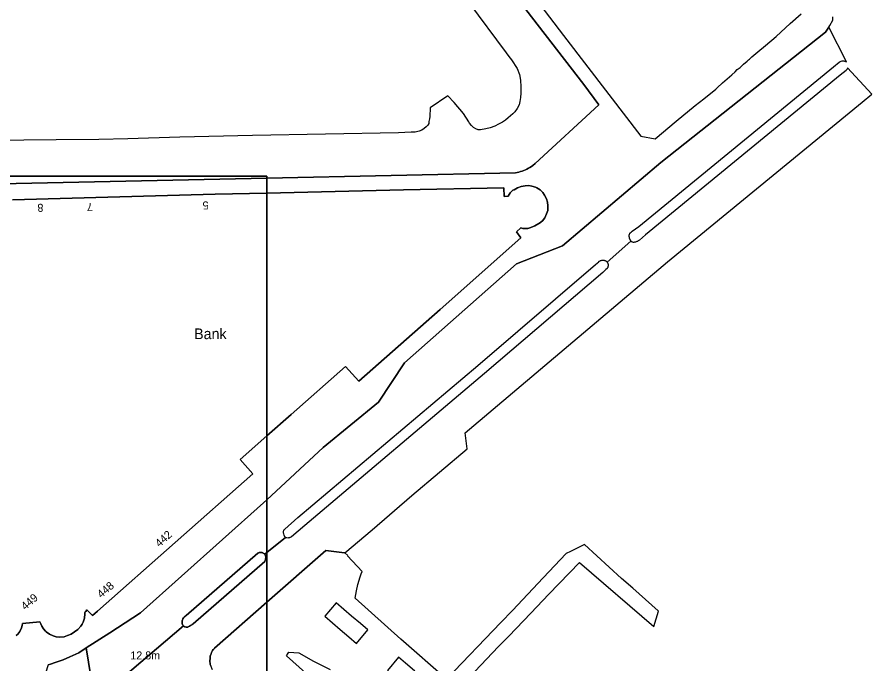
# Model space of a CAD drawing. Extents: x 529240 to 530363, y 179600 to 180767.
# Drawn here: x 530169.2 to 530329.3, y 180522.7 to 180643.8 of the extents above; entities that cross this region are included whole.
import ezdxf

# ---------------------------------------------------------------- set-up
doc = ezdxf.new("R2010")
doc.units = 0
for name, color, linetype in [('Building', 7, 'Continuous'), ('General surface', 7, 'Continuous'), ('Road Or Track', 7, 'Continuous'), ('Roadside', 7, 'Continuous'), ('Unclassified', 7, 'Continuous')]:
    doc.layers.add(name, color=color, linetype=linetype)

msp = doc.modelspace()

# ---------------------------------------------------------------- linework, layer by layer
at = {"layer": 'Building'}
msp.add_lwpolyline([(530216, 180610.87), (530216, 180565.37), (530220.55, 180569.4), (530230.7, 180578.35), (530233.2, 180575.65), (530248.45, 180589.05), (530263.6, 180602.5), (530262.75, 180603.6), (530263.6, 180604.35), (530263.95, 180604.25), (530264.4, 180604.2), (530264.9, 180604.25), (530265.45, 180604.4), (530266.2, 180604.7), (530266.95, 180605.15), (530267.05, 180605.2), (530267.65, 180605.65), (530268.05, 180606.25), (530268.4, 180606.95), (530268.6, 180607.6), (530268.65, 180608.3), (530268.65, 180608.45), (530268.55, 180609.15), (530268.35, 180609.8), (530268, 180610.45), (530267.7, 180610.95), (530267.2, 180611.45), (530266.55, 180611.85), (530266.3, 180611.95), (530265.65, 180612.15), (530265.05, 180612.25), (530264.35, 180612.2), (530263.65, 180612.1), (530262.95, 180611.85), (530262.3, 180611.5), (530262.1, 180611.4), (530261.6, 180610.9), (530261.2, 180610.3), (530260.45, 180610.2), (530260.4, 180611.85), (530241.6, 180611.45)], close=True, dxfattribs=at)
for points in [[(530216, 180610.87), (530241.6, 180611.45), (530260.4, 180611.85), (530260.45, 180610.2), (530261.2, 180610.3), (530261.6, 180610.9), (530262.1, 180611.4), (530262.3, 180611.5), (530262.95, 180611.85), (530263.65, 180612.1), (530264.35, 180612.2), (530265.05, 180612.25), (530265.65, 180612.15), (530266.3, 180611.95), (530266.55, 180611.85), (530267.2, 180611.45), (530267.7, 180610.95), (530268, 180610.45), (530268.35, 180609.8), (530268.55, 180609.15), (530268.65, 180608.45), (530268.65, 180608.3), (530268.6, 180607.6), (530268.4, 180606.95), (530268.05, 180606.25), (530267.65, 180605.65), (530267.05, 180605.2), (530266.95, 180605.15), (530266.2, 180604.7), (530265.45, 180604.4), (530264.9, 180604.25), (530264.4, 180604.2), (530263.95, 180604.25), (530263.6, 180604.35), (530262.75, 180603.6), (530263.6, 180602.5), (530248.45, 180589.05), (530233.2, 180575.65), (530230.7, 180578.35), (530220.55, 180569.4), (530216, 180565.37)], [(530169, 180528), (530169.3, 180528.2), (530169.7, 180528.75), (530170, 180529.4), (530170.15, 180529.85), (530170.2, 180530.25), (530173.45, 180530.55), (530173.6, 180530.15), (530173.8, 180529.75), (530174.1, 180529.25), (530174.5, 180528.8), (530174.65, 180528.65), (530175.25, 180528.2), (530175.95, 180527.9), (530176.5, 180527.75), (530177.2, 180527.65), (530178, 180527.75), (530178.65, 180527.95), (530179.3, 180528.25), (530179.95, 180528.65), (530180.55, 180529.1), (530181.1, 180529.7), (530181.35, 180530.1), (530181.55, 180530.5), (530181.8, 180531.25), (530181.9, 180532.05), (530181.9, 180532.25), (530181.95, 180532.4), (530182.05, 180532.5), (530182.25, 180532.8), (530183.3, 180531.75), (530184.25, 180532.55), (530213.35, 180558.25), (530211, 180560.95), (530216, 180565.37), (530216, 180610.87), (530206.3, 180610.65), (530168.35, 180609.6)], [(530168.35, 180609.6), (530206.3, 180610.65), (530216, 180610.87)], [(530216, 180565.37), (530211, 180560.95), (530213.35, 180558.25), (530184.25, 180532.55)], [(530184.25, 180532.55), (530183.3, 180531.75), (530182.25, 180532.8), (530182.05, 180532.5), (530181.95, 180532.4), (530181.9, 180532.25), (530181.9, 180532.05), (530181.8, 180531.25), (530181.55, 180530.5), (530181.35, 180530.1), (530181.1, 180529.7), (530180.55, 180529.1), (530179.95, 180528.65), (530179.3, 180528.25), (530178.65, 180527.95), (530178, 180527.75), (530177.2, 180527.65), (530176.5, 180527.75), (530175.95, 180527.9), (530175.25, 180528.2), (530174.65, 180528.65), (530174.5, 180528.8), (530174.1, 180529.25), (530173.8, 180529.75), (530173.6, 180530.15), (530173.45, 180530.55), (530170.2, 180530.25), (530170.15, 180529.85), (530170, 180529.4), (530169.7, 180528.75), (530169.3, 180528.2), (530169, 180528)]]:
    msp.add_lwpolyline(points, dxfattribs=at)
at = {"layer": 'General surface'}
for points in [[(530250.5, 180516.55), (530259.4, 180525.9), (530261.35, 180527.85), (530265.45, 180532.15), (530268.8, 180535.7), (530274.55, 180541.65), (530288.5, 180529.65), (530289.35, 180532.56), (530289.3, 180532.6), (530284.55, 180536.85), (530282.45, 180538.65), (530275.5, 180545), (530272.85, 180543.7), (530272.05, 180543.35), (530267.75, 180538.8), (530262, 180532.65), (530259.85, 180530.4), (530249.65, 180519.8), (530241.1, 180527.3), (530232.5, 180534.95), (530232.75, 180536.35), (530233.05, 180537.55), (530233.45, 180538.95), (530233.65, 180539.55), (530233.85, 180540), (530231.1, 180542.9), (530231.14, 180542.94), (530230.59, 180543.49), (530230.55, 180543.45), (530227.04, 180543.91), (530216, 180534.22), (530216, 180511.39)], [(530216, 180511.39), (530216, 180534.22), (530206.16, 180525.58), (530206.08, 180525.51), (530206.02, 180525.44), (530205.95, 180525.36), (530205.82, 180525.18), (530205.74, 180525.05), (530205.67, 180524.92), (530205.61, 180524.78), (530205.52, 180524.56), (530205.47, 180524.4), (530205.39, 180524.08), (530205.36, 180523.92), (530205.33, 180523.68), (530205.3, 180523.26), (530205.32, 180522.98), (530205.33, 180522.83), (530205.35, 180522.68), (530205.38, 180522.53)], [(530226.25, 180518.3), (530219.65, 180524.2), (530220, 180524.7), (530220.1, 180524.85), (530221.95, 180524.75), (530224.75, 180523.15), (530227.85, 180521.6)]]:
    msp.add_lwpolyline(points, dxfattribs=at)
for points in [[(530232.75, 180526.5), (530234.9, 180529.05), (530233.52, 180530.22), (530231.87, 180531.63), (530228.99, 180534.09), (530226.84, 180531.59), (530229.74, 180529.09), (530231.33, 180527.72)], [(530243.1, 180517.54), (530245.25, 180519.95), (530243.64, 180521.34), (530241.96, 180522.81), (530240.65, 180523.95), (530238.6, 180521.45), (530239.83, 180520.38), (530241.49, 180518.94)]]:
    msp.add_lwpolyline(points, close=True, dxfattribs=at)
at = {"layer": 'Road Or Track'}
for points in [[(530159.79, 180614), (530216, 180614), (530216, 180613.65), (530262.6, 180614.66), (530262.91, 180614.72), (530263.22, 180614.8), (530263.52, 180614.88), (530263.83, 180614.98), (530264.14, 180615.1), (530264.44, 180615.23), (530264.72, 180615.37), (530265, 180615.52), (530265.28, 180615.68), (530265.55, 180615.85), (530265.81, 180616.03), (530266.27, 180616.39), (530278.21, 180627.4), (530275.35, 180631.2), (530260.9, 180650)], [(530253.75, 180646.6), (530260.8, 180637.15), (530261.35, 180636.45), (530261.8, 180635.8), (530262.9, 180634.2), (530263.3, 180633.05), (530263.5, 180632), (530263.55, 180630.75), (530263.55, 180629.6), (530263.5, 180628.75), (530263.4, 180628), (530263.25, 180627.4), (530262.9, 180626.7), (530262.45, 180626.05), (530262.1, 180625.7), (530261.65, 180625.35), (530261.2, 180624.95), (530260.7, 180624.55), (530260.15, 180624.15), (530259.4, 180623.75), (530258.7, 180623.4), (530257.85, 180623.1), (530257, 180622.9), (530256, 180622.7), (530255.6, 180622.7), (530255.15, 180622.9), (530254.7, 180623.15), (530254.3, 180623.55), (530253.95, 180623.95), (530253.8, 180624.2), (530252.85, 180625.75), (530251.05, 180627.85), (530249.9, 180629.1), (530246.6, 180626.8), (530246.5, 180625.2), (530246.45, 180624.75), (530246.35, 180624.3), (530246.3, 180623.9), (530246.15, 180623.6), (530245.85, 180623.25), (530245.45, 180622.95), (530245, 180622.65), (530244.5, 180622.45), (530243.8, 180622.3), (530243, 180622.3), (530240.65, 180622.15), (530213.3, 180621.65), (530199.65, 180621.35), (530189.95, 180621), (530184.5, 180620.9), (530176.5, 180620.85), (530164.3, 180620.7)], [(530320.67, 180640.98), (530289.82, 180616.57), (530271.37, 180600.96), (530262.73, 180597.6), (530241.77, 180579.09), (530236.87, 180571.69), (530226.51, 180563.18), (530216, 180553.41)], [(530216, 180613.65), (530262.6, 180614.66), (530262.91, 180614.72), (530263.22, 180614.8), (530263.52, 180614.88), (530263.83, 180614.98), (530264.14, 180615.1), (530264.44, 180615.23), (530264.72, 180615.37), (530265, 180615.52), (530265.28, 180615.68), (530265.55, 180615.85), (530265.81, 180616.03), (530266.27, 180616.39)], [(530159.3, 180611.2), (530159.95, 180611.7), (530160.35, 180611.95), (530160.95, 180612.2), (530161.3, 180612.35), (530161.75, 180612.45), (530162.1, 180612.5), (530162.5, 180612.55), (530163.05, 180612.5), (530216, 180613.65)], [(530188.97, 180520.12), (530200.34, 180529.78), (530200.2, 180529.99), (530200.19, 180530.02), (530200.18, 180530.06), (530200.16, 180530.09), (530200.15, 180530.13), (530200.14, 180530.16), (530200.14, 180530.2), (530200.13, 180530.23), (530200.12, 180530.27), (530200.12, 180530.3), (530200.11, 180530.34), (530200.11, 180530.38), (530200.1, 180530.46), (530200.11, 180530.62), (530200.11, 180530.66), (530200.12, 180530.72), (530200.14, 180530.82), (530200.16, 180530.87), (530200.18, 180530.91), (530200.21, 180531.01), (530200.24, 180531.08), (530200.36, 180531.28), (530200.4, 180531.32), (530200.43, 180531.37), (530200.47, 180531.41), (530200.51, 180531.46), (530200.56, 180531.5), (530200.6, 180531.54), (530200.65, 180531.57), (530200.69, 180531.61), (530200.84, 180531.7), (530214.29, 180543.38), (530214.32, 180543.4), (530214.36, 180543.42), (530214.42, 180543.46), (530214.46, 180543.47), (530214.49, 180543.49), (530214.52, 180543.5), (530214.6, 180543.52), (530214.67, 180543.54), (530214.71, 180543.54), (530214.75, 180543.55), (530214.84, 180543.55), (530214.88, 180543.54), (530214.97, 180543.53), (530215.01, 180543.52), (530215.1, 180543.5), (530215.17, 180543.48), (530215.2, 180543.46), (530215.24, 180543.44), (530215.27, 180543.43), (530215.31, 180543.41), (530215.4, 180543.35), (530215.46, 180543.3), (530215.49, 180543.27), (530215.52, 180543.25), (530215.58, 180543.19), (530216, 180543.53), (530216, 180553.41), (530215.35, 180552.81), (530192.33, 180532.25), (530186.55, 180528.5), (530182.12, 180525.65), (530183.47, 180517.23)], [(530216, 180553.41), (530215.35, 180552.81), (530192.33, 180532.25), (530186.55, 180528.5), (530182.12, 180525.65)], [(530205.38, 180522.53), (530205.35, 180522.68), (530205.33, 180522.83), (530205.32, 180522.98), (530205.3, 180523.26), (530205.33, 180523.68), (530205.36, 180523.92), (530205.39, 180524.08), (530205.47, 180524.4), (530205.52, 180524.56), (530205.61, 180524.78), (530205.67, 180524.92), (530205.74, 180525.05), (530205.82, 180525.18), (530205.95, 180525.36), (530206.02, 180525.44), (530206.08, 180525.51), (530206.16, 180525.58), (530216, 180534.22), (530216, 180543.53), (530215.58, 180543.19), (530215.68, 180543.04), (530215.71, 180542.97), (530215.73, 180542.91), (530215.75, 180542.84), (530215.77, 180542.7), (530215.76, 180542.56), (530215.75, 180542.41), (530215.73, 180542.27), (530215.7, 180542.13), (530215.68, 180542.07), (530215.6, 180541.87), (530202.16, 180530.19), (530202, 180530.06), (530201.9, 180529.98), (530201.8, 180529.91), (530201.69, 180529.85), (530201.48, 180529.72), (530201.38, 180529.66), (530201.26, 180529.6), (530201.15, 180529.56), (530201.04, 180529.54), (530200.92, 180529.53), (530200.84, 180529.54), (530200.68, 180529.58), (530200.65, 180529.59), (530200.61, 180529.61), (530200.57, 180529.62), (530200.54, 180529.64), (530200.5, 180529.66), (530200.47, 180529.68), (530200.44, 180529.71), (530200.4, 180529.73), (530200.37, 180529.76), (530200.34, 180529.78), (530188.97, 180520.12)], [(530200.34, 180529.78), (530200.2, 180529.99), (530200.19, 180530.02), (530200.18, 180530.06), (530200.16, 180530.09), (530200.15, 180530.13), (530200.14, 180530.16), (530200.14, 180530.2), (530200.13, 180530.23), (530200.12, 180530.27), (530200.12, 180530.3), (530200.11, 180530.34), (530200.11, 180530.38), (530200.1, 180530.46), (530200.11, 180530.62), (530200.11, 180530.66), (530200.12, 180530.72), (530200.14, 180530.82), (530200.16, 180530.87), (530200.18, 180530.91), (530200.21, 180531.01), (530200.24, 180531.08), (530200.36, 180531.28), (530200.4, 180531.32), (530200.43, 180531.37), (530200.47, 180531.41), (530200.51, 180531.46), (530200.56, 180531.5), (530200.6, 180531.54), (530200.65, 180531.57), (530200.69, 180531.61), (530200.84, 180531.7), (530214.29, 180543.38), (530214.32, 180543.4), (530214.36, 180543.42), (530214.42, 180543.46), (530214.46, 180543.47), (530214.49, 180543.49), (530214.52, 180543.5), (530214.6, 180543.52), (530214.67, 180543.54), (530214.71, 180543.54), (530214.75, 180543.55), (530214.84, 180543.55), (530214.88, 180543.54), (530214.97, 180543.53), (530215.01, 180543.52), (530215.1, 180543.5), (530215.17, 180543.48), (530215.2, 180543.46), (530215.24, 180543.44), (530215.27, 180543.43), (530215.31, 180543.41), (530215.4, 180543.35), (530215.46, 180543.3), (530215.49, 180543.27), (530215.52, 180543.25), (530215.58, 180543.19)], [(530230.59, 180543.49), (530230.55, 180543.45), (530227.04, 180543.91), (530216, 180534.22)], [(530202.16, 180530.19), (530215.6, 180541.87)], [(530215.58, 180543.19), (530215.68, 180543.04), (530215.71, 180542.97), (530215.73, 180542.91), (530215.75, 180542.84), (530215.77, 180542.7), (530215.76, 180542.56), (530215.75, 180542.41), (530215.73, 180542.27), (530215.7, 180542.13), (530215.68, 180542.07), (530215.6, 180541.87)], [(530216, 180534.22), (530206.16, 180525.58), (530206.08, 180525.51), (530206.02, 180525.44), (530205.95, 180525.36), (530205.82, 180525.18), (530205.74, 180525.05), (530205.67, 180524.92), (530205.61, 180524.78), (530205.52, 180524.56), (530205.47, 180524.4), (530205.39, 180524.08), (530205.36, 180523.92), (530205.33, 180523.68), (530205.3, 180523.26), (530205.32, 180522.98), (530205.33, 180522.83), (530205.35, 180522.68), (530205.38, 180522.53), (530205.46, 180522.23), (530205.52, 180522.05), (530205.58, 180521.91), (530205.75, 180521.62)], [(530202.16, 180530.19), (530202, 180530.06), (530201.9, 180529.98), (530201.8, 180529.91), (530201.69, 180529.85), (530201.48, 180529.72), (530201.38, 180529.66), (530201.26, 180529.6), (530201.15, 180529.56), (530201.04, 180529.54), (530200.92, 180529.53), (530200.84, 180529.54), (530200.68, 180529.58), (530200.65, 180529.59), (530200.61, 180529.61), (530200.57, 180529.62), (530200.54, 180529.64), (530200.5, 180529.66), (530200.47, 180529.68), (530200.44, 180529.71), (530200.4, 180529.73), (530200.37, 180529.76), (530200.34, 180529.78)], [(530182.12, 180525.65), (530180.73, 180524.75), (530179.05, 180523.96), (530177.8, 180523.44), (530176.52, 180522.98), (530175.23, 180522.56), (530174.99, 180522.51)]]:
    msp.add_lwpolyline(points, dxfattribs=at)
for points in [[(530216, 180553.41), (530216, 180543.53), (530219.47, 180546.37), (530219.44, 180546.39), (530219.42, 180546.41), (530219.4, 180546.44), (530219.36, 180546.48), (530219.35, 180546.51), (530219.33, 180546.53), (530219.32, 180546.56), (530219.3, 180546.59), (530219.29, 180546.62), (530219.27, 180546.64), (530219.24, 180546.73), (530219.22, 180546.76), (530219.14, 180547), (530219.12, 180547.12), (530219.1, 180547.23), (530219.1, 180547.41), (530219.13, 180547.53), (530219.15, 180547.62), (530219.19, 180547.7), (530219.2, 180547.74), (530219.25, 180547.81), (530219.27, 180547.85), (530219.32, 180547.92), (530221.81, 180550.09), (530255.49, 180578.59), (530277.56, 180597.46), (530278.16, 180597.99), (530278.19, 180598.02), (530278.26, 180598.08), (530278.34, 180598.13), (530278.43, 180598.18), (530278.51, 180598.22), (530278.56, 180598.24), (530278.63, 180598.26), (530278.72, 180598.28), (530278.82, 180598.3), (530279.04, 180598.3), (530279.14, 180598.28), (530279.18, 180598.28), (530279.23, 180598.26), (530279.27, 180598.25), (530279.3, 180598.24), (530279.34, 180598.22), (530279.38, 180598.21), (530279.41, 180598.19), (530279.45, 180598.17), (530279.48, 180598.16), (530279.55, 180598.11), (530279.58, 180598.09), (530279.64, 180598.04), (530279.7, 180597.98), (530279.77, 180597.9), (530284.2, 180601.88), (530284.16, 180601.94), (530284.15, 180601.97), (530284.13, 180602), (530284.12, 180602.03), (530284.08, 180602.09), (530284.06, 180602.15), (530284.04, 180602.18), (530284.02, 180602.24), (530284, 180602.27), (530283.96, 180602.38), (530283.94, 180602.45), (530283.9, 180602.57), (530283.88, 180602.7), (530283.87, 180602.76), (530283.87, 180602.96), (530283.88, 180603.02), (530283.9, 180603.08), (530283.92, 180603.15), (530283.98, 180603.27), (530284, 180603.3), (530284.02, 180603.34), (530284.07, 180603.41), (530284.22, 180603.56), (530284.36, 180603.66), (530284.44, 180603.7), (530285.66, 180604.58), (530322.14, 180634.48), (530323.22, 180635.38), (530323.34, 180635.46), (530323.42, 180635.51), (530323.46, 180635.53), (530323.56, 180635.57), (530323.62, 180635.59), (530323.8, 180635.63), (530323.94, 180635.64), (530324.12, 180635.62), (530324.19, 180635.6), (530324.23, 180635.6), (530324.26, 180635.59), (530324.3, 180635.58), (530324.33, 180635.56), (530324.36, 180635.55), (530324.4, 180635.54), (530324.43, 180635.52), (530324.46, 180635.51), (530324.57, 180635.44), (530321.28, 180641.95), (530320.67, 180640.98), (530289.82, 180616.57), (530271.37, 180600.96), (530262.73, 180597.6), (530241.77, 180579.09), (530236.87, 180571.69), (530226.51, 180563.18)], [(530216, 180543.53), (530216, 180534.22), (530227.04, 180543.91), (530230.55, 180543.45), (530230.59, 180543.49), (530235.7, 180547.8), (530243.12, 180554.23), (530253.49, 180562.96), (530253.14, 180565.96), (530291.04, 180598), (530327.53, 180627.9), (530329.35, 180629.41), (530324.8, 180634.3), (530324.75, 180634.19), (530324.72, 180634.12), (530324.69, 180634.06), (530324.65, 180634), (530324.62, 180633.95), (530324.51, 180633.8), (530323.41, 180632.93), (530286.92, 180603.03), (530285.8, 180602.04), (530285.58, 180601.89), (530285.51, 180601.85), (530285.44, 180601.82), (530285.38, 180601.79), (530285.31, 180601.76), (530285.17, 180601.72), (530285.04, 180601.68), (530284.96, 180601.66), (530284.89, 180601.64), (530284.74, 180601.62), (530284.67, 180601.62), (530284.53, 180601.64), (530284.46, 180601.66), (530284.39, 180601.7), (530284.36, 180601.72), (530284.34, 180601.74), (530284.31, 180601.76), (530284.24, 180601.83), (530284.22, 180601.86), (530284.2, 180601.88), (530279.77, 180597.9), (530279.82, 180597.82), (530279.84, 180597.79), (530279.85, 180597.75), (530279.87, 180597.71), (530279.88, 180597.67), (530279.9, 180597.63), (530279.92, 180597.55), (530279.92, 180597.51), (530279.94, 180597.43), (530279.94, 180597.3), (530279.93, 180597.26), (530279.93, 180597.22), (530279.88, 180597.02), (530279.84, 180596.94), (530279.83, 180596.9), (530279.81, 180596.87), (530279.76, 180596.8), (530279.74, 180596.76), (530279.5, 180596.54), (530278.92, 180595.99), (530256.78, 180577.07), (530223.1, 180548.56), (530220.57, 180546.44), (530220.32, 180546.32), (530220.28, 180546.31), (530220.23, 180546.29), (530220.13, 180546.27), (530220.01, 180546.25), (530219.9, 180546.24), (530219.75, 180546.25), (530219.65, 180546.27), (530219.6, 180546.29), (530219.56, 180546.31), (530219.51, 180546.34), (530219.49, 180546.35), (530219.47, 180546.37)], [(530159.79, 180614), (530159.3, 180611.2), (530159.95, 180611.7), (530160.35, 180611.95), (530160.95, 180612.2), (530161.3, 180612.35), (530161.75, 180612.45), (530162.1, 180612.5), (530162.5, 180612.55), (530163.05, 180612.5), (530216, 180613.65), (530216, 180614)], [(530172.76, 180515.42), (530183.47, 180517.23), (530182.12, 180525.65), (530180.73, 180524.75), (530179.05, 180523.96), (530177.8, 180523.44), (530176.52, 180522.98), (530175.23, 180522.56), (530174.99, 180522.51)]]:
    msp.add_lwpolyline(points, close=True, dxfattribs=at)
at = {"layer": 'Roadside'}
for points in [[(530260.9, 180650), (530275.35, 180631.2), (530278.21, 180627.4), (530266.27, 180616.39), (530265.81, 180616.03), (530265.55, 180615.85), (530265.28, 180615.68), (530265, 180615.52), (530264.72, 180615.37), (530264.44, 180615.23), (530264.14, 180615.1), (530263.83, 180614.98), (530263.52, 180614.88), (530263.22, 180614.8), (530262.91, 180614.72), (530262.6, 180614.66), (530216, 180613.65), (530216, 180610.87), (530241.6, 180611.45), (530260.4, 180611.85), (530260.45, 180610.2), (530261.2, 180610.3), (530261.6, 180610.9), (530262.1, 180611.4), (530262.3, 180611.5), (530262.95, 180611.85), (530263.65, 180612.1), (530264.35, 180612.2), (530265.05, 180612.25), (530265.65, 180612.15), (530266.3, 180611.95), (530266.55, 180611.85), (530267.2, 180611.45), (530267.7, 180610.95), (530268, 180610.45), (530268.35, 180609.8), (530268.55, 180609.15), (530268.65, 180608.45), (530268.65, 180608.3), (530268.6, 180607.6), (530268.4, 180606.95), (530268.05, 180606.25), (530267.65, 180605.65), (530267.05, 180605.2), (530266.95, 180605.15), (530266.2, 180604.7), (530265.45, 180604.4), (530264.9, 180604.25), (530264.4, 180604.2), (530263.95, 180604.25), (530263.6, 180604.35), (530262.75, 180603.6), (530263.6, 180602.5), (530248.45, 180589.05), (530233.2, 180575.65), (530230.7, 180578.35), (530220.55, 180569.4), (530216, 180565.37), (530216, 180553.41), (530226.51, 180563.18), (530236.87, 180571.69), (530241.77, 180579.09), (530262.73, 180597.6), (530271.37, 180600.96), (530289.82, 180616.57), (530320.67, 180640.98), (530321.28, 180641.95), (530321.47, 180642.26), (530322, 180643.24), (530322.03, 180643.37), (530322.04, 180643.45), (530322.04, 180643.8), (530322.03, 180643.88)], [(530264.5, 180649.7), (530271.55, 180640.4), (530280.05, 180629.3), (530286.05, 180621.5), (530288.75, 180621.05), (530292.7, 180624.35), (530296.25, 180627.25), (530297.05, 180627.9), (530297.85, 180628.5), (530300.1, 180630.35), (530300.35, 180630.6), (530301.35, 180631.5), (530303.1, 180633), (530303.75, 180633.6), (530304.1, 180634), (530304.65, 180634.4), (530305.3, 180635), (530305.95, 180635.55), (530306.2, 180635.8), (530306.4, 180635.95), (530306.85, 180636.4), (530307.95, 180637.3), (530309.4, 180638.5), (530311.4, 180640.2), (530314.05, 180642.6), (530316.1, 180644.45)], [(530168.35, 180609.6), (530206.3, 180610.65), (530216, 180610.87), (530216, 180613.65), (530163.05, 180612.5)], [(530175.23, 180522.56), (530176.52, 180522.98), (530177.8, 180523.44), (530179.05, 180523.96), (530180.73, 180524.75), (530182.12, 180525.65), (530186.55, 180528.5), (530192.33, 180532.25), (530215.35, 180552.81), (530216, 180553.41), (530216, 180565.37), (530211, 180560.95), (530213.35, 180558.25), (530184.25, 180532.55), (530183.3, 180531.75), (530182.25, 180532.8), (530182.05, 180532.5), (530181.95, 180532.4), (530181.9, 180532.25), (530181.9, 180532.05), (530181.8, 180531.25), (530181.55, 180530.5), (530181.35, 180530.1), (530181.1, 180529.7), (530180.55, 180529.1), (530179.95, 180528.65), (530179.3, 180528.25), (530178.65, 180527.95), (530178, 180527.75), (530177.2, 180527.65), (530176.5, 180527.75), (530175.95, 180527.9), (530175.25, 180528.2), (530174.65, 180528.65), (530174.5, 180528.8), (530174.1, 180529.25), (530173.8, 180529.75), (530173.6, 180530.15), (530173.45, 180530.55), (530170.2, 180530.25), (530170.15, 180529.85), (530170, 180529.4), (530169.7, 180528.75), (530169.3, 180528.2), (530169, 180528)]]:
    msp.add_lwpolyline(points, dxfattribs=at)
msp.add_lwpolyline([(530215.58, 180543.19), (530215.52, 180543.25), (530215.49, 180543.27), (530215.46, 180543.3), (530215.4, 180543.35), (530215.31, 180543.41), (530215.27, 180543.43), (530215.24, 180543.44), (530215.2, 180543.46), (530215.17, 180543.48), (530215.1, 180543.5), (530215.01, 180543.52), (530214.97, 180543.53), (530214.88, 180543.54), (530214.84, 180543.55), (530214.75, 180543.55), (530214.71, 180543.54), (530214.67, 180543.54), (530214.6, 180543.52), (530214.52, 180543.5), (530214.49, 180543.49), (530214.46, 180543.47), (530214.42, 180543.46), (530214.36, 180543.42), (530214.32, 180543.4), (530214.29, 180543.38), (530200.84, 180531.7), (530200.69, 180531.61), (530200.65, 180531.57), (530200.6, 180531.54), (530200.56, 180531.5), (530200.51, 180531.46), (530200.47, 180531.41), (530200.43, 180531.37), (530200.4, 180531.32), (530200.36, 180531.28), (530200.24, 180531.08), (530200.21, 180531.01), (530200.18, 180530.91), (530200.16, 180530.87), (530200.14, 180530.82), (530200.12, 180530.72), (530200.11, 180530.66), (530200.11, 180530.62), (530200.1, 180530.46), (530200.11, 180530.38), (530200.11, 180530.34), (530200.12, 180530.3), (530200.12, 180530.27), (530200.13, 180530.23), (530200.14, 180530.2), (530200.14, 180530.16), (530200.15, 180530.13), (530200.16, 180530.09), (530200.18, 180530.06), (530200.19, 180530.02), (530200.2, 180529.99), (530200.34, 180529.78), (530200.37, 180529.76), (530200.4, 180529.73), (530200.44, 180529.71), (530200.47, 180529.68), (530200.5, 180529.66), (530200.54, 180529.64), (530200.57, 180529.62), (530200.61, 180529.61), (530200.65, 180529.59), (530200.68, 180529.58), (530200.84, 180529.54), (530200.92, 180529.53), (530201.04, 180529.54), (530201.15, 180529.56), (530201.26, 180529.6), (530201.38, 180529.66), (530201.48, 180529.72), (530201.69, 180529.85), (530201.8, 180529.91), (530201.9, 180529.98), (530202, 180530.06), (530202.16, 180530.19), (530215.6, 180541.87), (530215.68, 180542.07), (530215.7, 180542.13), (530215.73, 180542.27), (530215.75, 180542.41), (530215.76, 180542.56), (530215.77, 180542.7), (530215.75, 180542.84), (530215.73, 180542.91), (530215.71, 180542.97), (530215.68, 180543.04)], close=True, dxfattribs=at)
at = {"layer": 'Unclassified'}
for points in [[(530216, 180543.53), (530219.47, 180546.37)], [(530215.58, 180543.19), (530216, 180543.53)], [(530200.34, 180529.78), (530188.97, 180520.12)], [(530183.47, 180517.23), (530182.12, 180525.65)]]:
    msp.add_lwpolyline(points, dxfattribs=at)

# ---------------------------------------------------------------- texts
for s, rotation, p in [('5', 181.4, (530205.03, 180609.31)), ('8', 181.4, (530174.09, 180608.86)), ('7', 181.4, (530183.35, 180609)), ('442', 41.7, (530195.85, 180544.45)), ('448', 40.5, (530184.95, 180534.9)), ('449', 40.6, (530170.7, 180532.65))]:
    msp.add_text(s, height=1.5, rotation=rotation, dxfattribs=at).set_placement(p)
for s, height, p in [('Bank', 2, (530202.35, 180583.5)), ('12.8m', 1.5, (530190.4, 180523.5))]:
    msp.add_text(s, height=height, dxfattribs=at).set_placement(p)

doc.saveas('drawing.dxf')
